// Mitsubishi GX Works2 project: 52.用编码器测量机床位置   PLC: FX3U/FX3UC

PROGRAM MAIN
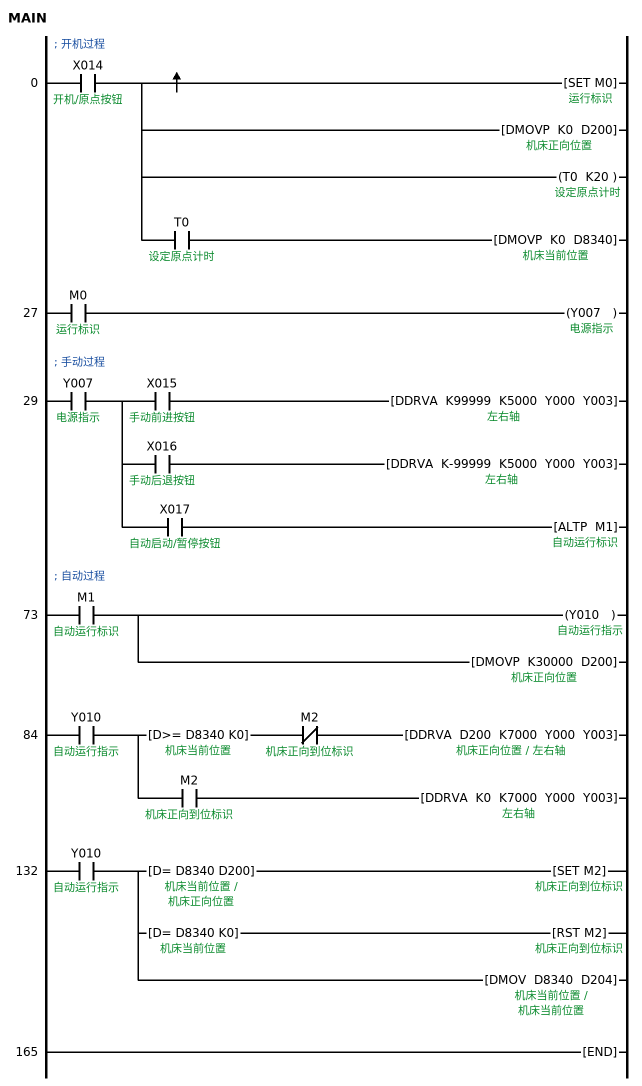
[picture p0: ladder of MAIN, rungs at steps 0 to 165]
; 开机过程
0     LD      X014  ; 开机/原点按钮
      MPS
      MEP
      SET     M0  ; 运行标识
      MPP
      DMOVP   K0 D200  ; 机床正向位置
      OUT     T0 K20  ; 设定原点计时
      AND     T0  ; 设定原点计时
      DMOVP   K0 D8340  ; 机床当前位置
27    LD      M0  ; 运行标识
      OUT     Y007  ; 电源指示
; 手动过程
29    LD      Y007  ; 电源指示
      MPS
      AND     X015  ; 手动前进按钮
      DDRVA   K99999 K5000 Y000 Y003  ; 左右轴
      MRD
      AND     X016  ; 手动后退按钮
      DDRVA   K-99999 K5000 Y000 Y003
      MPP
      AND     X017  ; 自动启动/暂停按钮
      ALTP    M1  ; 自动运行标识
; 自动过程
73    LD      M1  ; 自动运行标识
      OUT     Y010  ; 自动运行指示
      DMOVP   K30000 D200
84    LD      Y010  ; 自动运行指示
      MPS
      ANDD>=  D8340 K0  ; 机床当前位置
      ANI     M2  ; 机床正向到位标识
      DDRVA   D200 K7000 Y000 Y003
      MPP
      AND     M2  ; 机床正向到位标识
      DDRVA   K0 K7000 Y000 Y003
132   LD      Y010  ; 自动运行指示
      MPS
      ANDD=   D8340 D200  ; 机床当前位置 / 机床正向位置
      SET     M2  ; 机床正向到位标识
      MRD
      ANDD=   D8340 K0  ; 机床当前位置
      RST     M2  ; 机床正向到位标识
      MPP
      DMOV    D8340 D204  ; 机床当前位置
165   END
END_PROGRAM

// device comments not shown above
M3  ; 暂停标识
T1  ; 自动启动定时
C0  ; 启动/暂停键计次
D1  ; 按键次数
D202  ; 机床反向位置
